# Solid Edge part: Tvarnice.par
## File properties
Author: jachy
Template: iso metric part.par
Last saved by: jachy
Revision: 3
Application: Solid Edge
Username: jachy
Typ obsahu dokumentu: 0
Hustota: 0,000 kg/m^3
Přesnost: 0,990
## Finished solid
Body 1: sheet body, 2521 faces, 6525 edges, 4040 vertices.
  Faces by surface: spline 1083, plane 653, cylinder 489, torus 122, sphere 100, swept 45, cone 27, spun 2
  Edges by curve: curve on surface 4261, spline 804, line 734, circle 677, ellipse 31, intersection 18
Bounding box of the edges (mm; curved faces can reach further): 336.284 x 150.022 x 76.204, from (-69.6311, -58.9438, -37.9018) to (266.6529, 91.0786, 38.3027).
Cylindrical faces by radius (mm): R0.102 x1, R0.5 x32, R0.5096 x1, R0.51 x66, R0.612 x1, R1.0199 x1, R1.02 x92, R1.0201 x2, R1.0205 x1, R1.0513 x1, R1.275 x1, R1.53 x3, R2.04 x78, R2.0402 x1, R2.0405 x1, R3.06 x1, R3.0615 x1, R4.045 x1, R5.1 x1, R5.5 x4, R8 x4, R8.2197 x1, R8.5 x4, R9.094 x1, R9.4736 x1, R9.7894 x1, R10.1999 x1, R10.2 x1, R11.0162 x1, R11.8859 x1, R12.1916 x1, R14.8067 x1, R15.3161 x1, R15.3581 x1, R15.6929 x1, R17.0011 x1, R17.6606 x1, R19.488 x1, R22.1672 x1, R22.4356 x1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
Conical faces (half-angle, radius in mm at the cone's reference point): 3.9476 deg R377.6882 x1, 4.9974 deg R308.6475 x1, 4.9993 deg R2.0814 x1, 5 deg R1.7577 x1, 5 deg R2.04 x1, 5 deg R2.0572 x1, 5 deg R2.0955 x1, 5 deg R2.618 x1, 5 deg R3.06 x2, 5.0008 deg R3.5688 x1, 5.0011 deg R241.9552 x1, 5.0029 deg R52.9185 x1, 5.0554 deg R5.4268 x1, 5.6615 deg R279.929 x1, 6.9885 deg R387.1824 x1, 10 deg R2.04 x5, 37.6634 deg R323.043 x1, 39.4714 deg R13.298 x1, 44.6144 deg R1.9511 x1, 45.1692 deg R1.9435 x1, 45.1767 deg R1.9433 x1, 55.8554 deg R117.2753 x1
Toroidal faces (ring radius, tube radius in mm): R1.0385 r1.0208 x1, R1.0469 r1.0212 x1, R1.3573 r0.5098 x1, R1.5319 r0.5095 x1, R1.5338 r0.5095 x1, R1.5791 r0.5099 x1, R1.6121 r0.51 x5, R1.6605 r0.5099 x1, R1.6946 r0.5099 x1, R1.8576 r1.02 x2, R2.2103 r0.51 x1, R2.4035 r0.51 x1, R2.4529 r0.5099 x1, R2.4563 r0.5099 x1, R2.4596 r0.5098 x1, R2.5297 r0.51 x1, R2.5393 r0.5098 x1, R2.5418 r0.5098 x1, R2.5437 r0.5098 x1, R2.5461 r0.5098 x1, R2.5468 r0.5099 x1, R2.5554 r0.5095 x1, R2.558 r0.5094 x1, R2.5594 r0.5098 x1, R2.5919 r0.51 x1, R2.703 r0.51 x1, R2.719 r0.5097 x1, R2.7413 r0.51 x1, R2.775 r0.51 x1, R2.8276 r0.51 x5, R3.0184 r0.51 x1, R3.2638 r0.51 x1, R3.5207 r0.51 x1, R3.6071 r0.5096 x1, R4.1891 r0.5099 x1, R6.0267 r0.51 x1, R7.5 r0.5 x4, R8 r0.5 x4, R8.5598 r0.51 x1, R9.9836 r0.51 x1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
Spherical faces by radius (mm): R0.5099 x1, R0.51 x41, R0.5138 x1, R0.5151 x1, R1.02 x50, R1.0204 x1, R259.4227 x1, R276.4558 x1, R322.8007 x1, R328.3292 x1, R6403.835 x1
Planar faces by normal: +y 4, -y 3, oblique 646
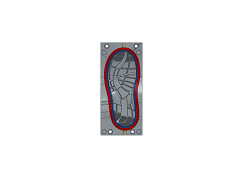
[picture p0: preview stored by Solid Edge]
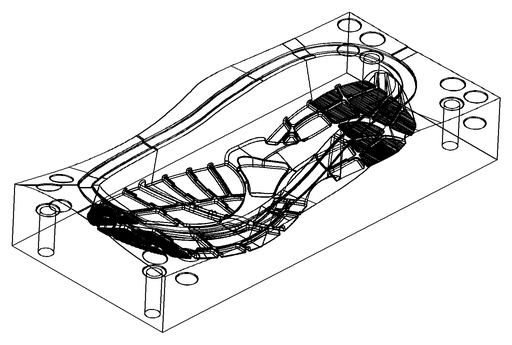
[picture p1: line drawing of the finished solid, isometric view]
